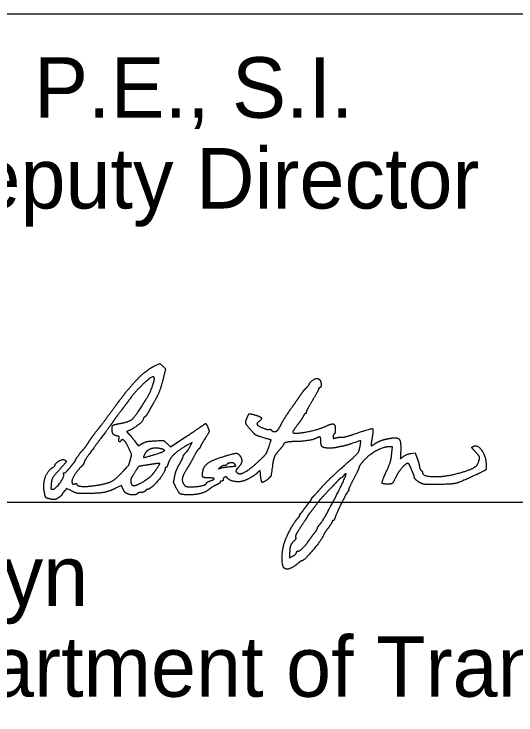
# Model space of a CAD drawing. Extents: x -6.2 to 37.4, y 0.2 to 22.2.
# Drawn here: x 25.269 to 26.43, y 7.512 to 9.134 of the extents above; entities that cross this region are included whole.
import ezdxf

# ---------------------------------------------------------------- set-up
doc = ezdxf.new("R2010")
doc.units = 0
doc.layers.add('SH_Data', color=7, linetype='Continuous')
doc.layers.add('SH_Text', color=7, linetype='Continuous')

msp = doc.modelspace()

# ---------------------------------------------------------------- linework, layer by layer
at = {"layer": 'SH_Data'}
for p, q in [((24.1087, 9.1337), (27.6087, 9.1337)), ((24.1087, 8.0042), (27.6087, 8.0042))]:
    msp.add_line(p, q, dxfattribs=at)
for points in [[(25.594, 8.3194), (25.6066, 8.3253), (25.613, 8.3189), (25.6194, 8.3126), (25.615, 8.2939)], [(25.5341, 8.1695), (25.5291, 8.1679), (25.5342, 8.1627)], [(25.5479, 8.1461), (25.5564, 8.1345), (25.5652, 8.1398)], [(25.623, 8.1398), (25.6312, 8.1321), (25.6674, 8.1563)], [(25.6769, 8.1345), (25.6814, 8.1424), (25.6759, 8.1395)], [(26.1428, 8.1186), (26.1443, 8.1324), (26.1365, 8.1324)], [(26.1866, 8.117), (26.1963, 8.1185), (26.2014, 8.105)], [(25.8387, 8.0708), (25.838, 8.0776), (25.8322, 8.0725)], [(25.4024, 8.0302), (25.3909, 8.0359), (25.3859, 8.0301)], [(25.5211, 8.0352), (25.5177, 8.0432), (25.5039, 8.0364)], [(25.9064, 7.8847), (25.9064, 7.8753), (25.914, 7.8796)]]:
    msp.add_lwpolyline(points, dxfattribs=at)
for points in [[(25.5044, 8.2276), (25.5341, 8.2682), (25.5759, 8.311), (25.594, 8.3194)], [(25.5926, 8.2936), (25.5889, 8.2973), (25.5504, 8.2616), (25.535, 8.2403)], [(25.5743, 8.2416), (25.5837, 8.2565), (25.5957, 8.2905), (25.5926, 8.2936)], [(25.615, 8.2939), (25.61, 8.2727), (25.6008, 8.2491), (25.5914, 8.2332)], [(25.952, 8.2775), (25.952, 8.2803), (25.9652, 8.2906), (25.969, 8.2907)], [(25.969, 8.2907), (25.971, 8.2907), (25.974, 8.2895), (25.9756, 8.2879)], [(25.9756, 8.2879), (25.979, 8.2844), (25.9794, 8.2692), (25.976, 8.2692)], [(25.9454, 8.2694), (25.9491, 8.273), (25.952, 8.2767), (25.952, 8.2775)], [(25.9317, 8.2522), (25.9356, 8.258), (25.9418, 8.2658), (25.9454, 8.2694)], [(25.9736, 8.2667), (25.9736, 8.2653), (25.9672, 8.2532), (25.9592, 8.2398)], [(25.976, 8.2692), (25.9747, 8.2692), (25.9736, 8.268), (25.9736, 8.2667)], [(25.535, 8.2403), (25.5314, 8.2353), (25.522, 8.2226), (25.514, 8.2122)], [(25.5637, 8.2249), (25.567, 8.2301), (25.5717, 8.2376), (25.5743, 8.2416)], [(25.91, 8.2212), (25.918, 8.2324), (25.9277, 8.2464), (25.9317, 8.2522)], [(25.9592, 8.2398), (25.9513, 8.2264), (25.9448, 8.214), (25.9448, 8.2123)], [(25.4643, 8.1741), (25.4732, 8.1854), (25.4912, 8.2095), (25.5044, 8.2276)], [(25.5139, 8.1863), (25.5345, 8.19), (25.5486, 8.2009), (25.5637, 8.2249)], [(25.5914, 8.2332), (25.5878, 8.2272), (25.5826, 8.2181), (25.5798, 8.2128)], [(25.514, 8.2122), (25.5061, 8.2017), (25.498, 8.1907), (25.496, 8.1877)], [(25.5798, 8.2128), (25.5769, 8.2075), (25.5731, 8.2023), (25.5713, 8.2013)], [(25.808, 8.1995), (25.8117, 8.2085), (25.8149, 8.2095), (25.8276, 8.2057)], [(25.8276, 8.2057), (25.8396, 8.2022), (25.8424, 8.196), (25.8348, 8.1902)], [(25.8887, 8.1876), (25.8925, 8.1948), (25.9021, 8.21), (25.91, 8.2212)], [(25.9428, 8.2092), (25.9418, 8.2092), (25.9394, 8.2062), (25.9376, 8.2026)], [(25.9448, 8.2123), (25.9448, 8.2106), (25.9439, 8.2092), (25.9428, 8.2092)], [(25.568, 8.1959), (25.568, 8.1921), (25.5423, 8.1721), (25.5341, 8.1695)], [(25.5713, 8.2013), (25.5695, 8.2002), (25.568, 8.1978), (25.568, 8.1959)], [(25.8178, 8.17), (25.8063, 8.1831), (25.804, 8.1899), (25.808, 8.1995)], [(25.8348, 8.1902), (25.832, 8.1881), (25.8305, 8.1853), (25.8315, 8.1839)], [(25.9376, 8.2026), (25.9358, 8.1989), (25.9297, 8.1899), (25.924, 8.1824)], [(25.4427, 8.1447), (25.4457, 8.1495), (25.4554, 8.1628), (25.4643, 8.1741)], [(25.496, 8.1877), (25.4941, 8.1847), (25.4787, 8.1638), (25.4619, 8.1412)], [(25.496, 8.1741), (25.496, 8.181), (25.5002, 8.1838), (25.5139, 8.1863)], [(25.507, 8.1577), (25.4999, 8.1595), (25.496, 8.1652), (25.496, 8.1741)], [(25.6674, 8.1563), (25.6873, 8.1695), (25.7049, 8.1814), (25.7065, 8.1828)], [(25.7065, 8.1828), (25.7111, 8.1865), (25.7135, 8.1857), (25.7165, 8.1791)], [(25.7165, 8.1791), (25.7208, 8.1694), (25.7199, 8.1653), (25.7096, 8.1495)], [(25.8315, 8.1839), (25.8342, 8.1801), (25.8541, 8.1719), (25.8587, 8.1727)], [(25.8794, 8.1714), (25.8807, 8.173), (25.8848, 8.1803), (25.8887, 8.1876)], [(25.924, 8.1824), (25.9183, 8.1749), (25.9136, 8.1677), (25.9136, 8.1663)], [(25.9136, 8.1663), (25.9136, 8.161), (25.9733, 8.172), (25.9912, 8.1805)], [(25.9912, 8.1805), (26.0042, 8.1867), (26.012, 8.1836), (26.012, 8.1722)], [(26.0544, 8.1615), (26.0947, 8.1753), (26.1007, 8.1737), (26.0965, 8.1498)], [(25.5121, 8.1515), (25.513, 8.155), (25.5118, 8.1565), (25.507, 8.1577)], [(25.5342, 8.1627), (25.537, 8.1599), (25.5432, 8.1524), (25.5479, 8.1461)], [(25.8412, 8.1549), (25.8305, 8.158), (25.8256, 8.1612), (25.8178, 8.17)], [(25.8587, 8.1727), (25.861, 8.1731), (25.8635, 8.1723), (25.8644, 8.1709)], [(25.8644, 8.1709), (25.8665, 8.1674), (25.8766, 8.1677), (25.8794, 8.1714)], [(26.0096, 8.1624), (26.0083, 8.1616), (26.0072, 8.1587), (26.0072, 8.1561)], [(26.012, 8.1722), (26.012, 8.1676), (26.011, 8.1632), (26.0096, 8.1624)], [(26.0256, 8.1544), (26.0297, 8.1543), (26.0427, 8.1574), (26.0544, 8.1615)], [(25.4264, 8.1229), (25.433, 8.1302), (25.4373, 8.1359), (25.4427, 8.1447)], [(25.4619, 8.1412), (25.4451, 8.1185), (25.4313, 8.0984), (25.4312, 8.0964)], [(25.5164, 8.1467), (25.514, 8.1428), (25.5108, 8.1464), (25.5121, 8.1515)], [(25.5352, 8.1281), (25.5291, 8.1418), (25.5193, 8.1514), (25.5164, 8.1467)], [(25.5652, 8.1398), (25.5718, 8.1436), (25.5793, 8.1453), (25.5945, 8.1462)], [(25.5945, 8.1462), (25.6148, 8.1474), (25.6149, 8.1473), (25.623, 8.1398)], [(25.7096, 8.1495), (25.7044, 8.1413), (25.7, 8.1337), (25.7, 8.1326)], [(25.858, 8.1311), (25.8637, 8.148), (25.8633, 8.1485), (25.8412, 8.1549)], [(25.9163, 8.1444), (25.9048, 8.1444), (25.892, 8.1406), (25.892, 8.1372)], [(25.967, 8.1518), (25.9614, 8.1488), (25.9312, 8.1444), (25.9163, 8.1444)], [(25.9784, 8.147), (25.9784, 8.1544), (25.9748, 8.1559), (25.967, 8.1518)], [(25.9978, 8.1294), (25.9854, 8.1294), (25.9784, 8.1357), (25.9784, 8.147)], [(26.0072, 8.1561), (26.0072, 8.1522), (26.0083, 8.1516), (26.0126, 8.153)], [(26.0126, 8.153), (26.0156, 8.1539), (26.0214, 8.1546), (26.0256, 8.1544)], [(26.0697, 8.1348), (26.0718, 8.1463), (26.07, 8.1467), (26.049, 8.1395)], [(26.0965, 8.1498), (26.0952, 8.1422), (26.0945, 8.1356), (26.0949, 8.1351)], [(26.1025, 8.139), (26.1097, 8.144), (26.128, 8.1504), (26.1416, 8.1525)], [(26.1416, 8.1525), (26.1563, 8.1548), (26.1639, 8.1444), (26.1632, 8.1231)], [(25.5385, 8.1036), (25.5411, 8.1134), (25.5408, 8.1156), (25.5352, 8.1281)], [(25.6062, 8.1285), (25.5954, 8.1306), (25.578, 8.1256), (25.5737, 8.119)], [(25.5956, 8.1149), (25.6149, 8.1208), (25.6189, 8.1259), (25.6062, 8.1285)], [(25.6759, 8.1395), (25.6525, 8.127), (25.6297, 8.1063), (25.6256, 8.0938)], [(25.6641, 8.1164), (25.6696, 8.1224), (25.6721, 8.1259), (25.6769, 8.1345)], [(25.6965, 8.1276), (25.6945, 8.126), (25.6914, 8.1218), (25.6896, 8.1183)], [(25.7, 8.1326), (25.7, 8.1315), (25.6984, 8.1292), (25.6965, 8.1276)], [(25.8397, 8.1038), (25.8502, 8.1138), (25.8543, 8.12), (25.858, 8.1311)], [(25.8827, 8.1252), (25.8742, 8.1157), (25.8685, 8.1031), (25.8669, 8.0904)], [(25.892, 8.1372), (25.892, 8.1363), (25.8878, 8.1309), (25.8827, 8.1252)], [(26.0144, 8.1308), (26.0111, 8.13), (26.0036, 8.1294), (25.9978, 8.1294)], [(26.0276, 8.1334), (26.0237, 8.1328), (26.0177, 8.1316), (26.0144, 8.1308)], [(26.0248, 8.0819), (26.0603, 8.1134), (26.0672, 8.1216), (26.0697, 8.1348)], [(26.049, 8.1395), (26.0412, 8.1368), (26.0316, 8.1341), (26.0276, 8.1334)], [(26.1365, 8.1324), (26.1238, 8.1324), (26.09, 8.114), (26.0778, 8.1004)], [(26.0949, 8.1351), (26.0954, 8.1346), (26.0988, 8.1364), (26.1025, 8.139)], [(26.3332, 8.1238), (26.3279, 8.1295), (26.3277, 8.1321), (26.3323, 8.1339)], [(26.3323, 8.1339), (26.3409, 8.1372), (26.3594, 8.1122), (26.3604, 8.096)], [(25.412, 8.1024), (25.412, 8.104), (25.4212, 8.117), (25.4264, 8.1229)], [(25.5737, 8.119), (25.5667, 8.1082), (25.5712, 8.1074), (25.5956, 8.1149)], [(25.6517, 8.0923), (25.6561, 8.0999), (25.6599, 8.1076), (25.6602, 8.1093)], [(25.6602, 8.1093), (25.6604, 8.1111), (25.6622, 8.1142), (25.6641, 8.1164)], [(25.6896, 8.1183), (25.6815, 8.1029), (25.6737, 8.0892), (25.6676, 8.0794)], [(25.7434, 8.1066), (25.7753, 8.1172), (25.7887, 8.1176), (25.7937, 8.1082)], [(26.1281, 8.0707), (26.1372, 8.0906), (26.1412, 8.1038), (26.1428, 8.1186)], [(26.1632, 8.1231), (26.1625, 8.1048), (26.1623, 8.105), (26.1701, 8.1105)], [(26.1701, 8.1105), (26.1739, 8.1132), (26.1813, 8.1161), (26.1866, 8.117)], [(26.3424, 8.0947), (26.3463, 8.1065), (26.3448, 8.1114), (26.3332, 8.1238)], [(25.3641, 8.0904), (25.3641, 8.0941), (25.3809, 8.1041), (25.3847, 8.1026)], [(25.3847, 8.1026), (25.3906, 8.1003), (25.3884, 8.0955), (25.374, 8.0795)], [(25.3975, 8.0832), (25.4029, 8.0898), (25.4083, 8.0965), (25.4096, 8.0981)], [(25.4096, 8.0981), (25.411, 8.0997), (25.412, 8.1016), (25.412, 8.1024)], [(25.4312, 8.0964), (25.4312, 8.0944), (25.4278, 8.0896), (25.4239, 8.0857)], [(25.5188, 8.0731), (25.5349, 8.0907), (25.5352, 8.0912), (25.5385, 8.1036)], [(25.5938, 8.0928), (25.5882, 8.0919), (25.5804, 8.0907), (25.5764, 8.0901)], [(25.5988, 8.0811), (25.6067, 8.0925), (25.6057, 8.0947), (25.5938, 8.0928)], [(25.6256, 8.0938), (25.6239, 8.0886), (25.6216, 8.0844), (25.6205, 8.0844)], [(25.6408, 8.0644), (25.6424, 8.0721), (25.6473, 8.0846), (25.6517, 8.0923)], [(25.7058, 8.0756), (25.7079, 8.0868), (25.7241, 8.1002), (25.7434, 8.1066)], [(25.7796, 8.0924), (25.7768, 8.0958), (25.7633, 8.095), (25.7611, 8.0913)], [(25.7636, 8.086), (25.7804, 8.0876), (25.7828, 8.0885), (25.7796, 8.0924)], [(25.7827, 8.075), (25.7881, 8.0663), (25.8148, 8.0798), (25.8397, 8.1038)], [(25.7937, 8.1082), (25.797, 8.1021), (25.7936, 8.0908), (25.7861, 8.0829)], [(26.0778, 8.1004), (26.072, 8.0939), (26.0672, 8.0874), (26.0672, 8.0858)], [(26.1797, 8.094), (26.1753, 8.094), (26.1571, 8.0735), (26.1524, 8.0633)], [(26.1852, 8.0874), (26.1838, 8.091), (26.1812, 8.094), (26.1797, 8.094)], [(26.2014, 8.105), (26.2042, 8.0975), (26.2064, 8.0894), (26.2064, 8.0869)], [(26.2935, 8.0704), (26.3172, 8.0766), (26.3401, 8.088), (26.3424, 8.0947)], [(26.3604, 8.096), (26.3613, 8.0806), (26.3586, 8.0775), (26.3352, 8.0665)], [(25.3392, 8.0287), (25.3362, 8.0473), (25.347, 8.0773), (25.3594, 8.085)], [(25.374, 8.0795), (25.3604, 8.0644), (25.3554, 8.0542), (25.3548, 8.0404)], [(25.3594, 8.085), (25.3619, 8.0866), (25.3641, 8.089), (25.3641, 8.0904)], [(25.3852, 8.0719), (25.3866, 8.0715), (25.3922, 8.0766), (25.3975, 8.0832)], [(25.4239, 8.0857), (25.414, 8.076), (25.4016, 8.0539), (25.4034, 8.0492)], [(25.5764, 8.0901), (25.5587, 8.0876), (25.5566, 8.0864), (25.5494, 8.0752)], [(25.569, 8.0525), (25.5801, 8.0594), (25.5911, 8.07), (25.5988, 8.0811)], [(25.6184, 8.0814), (25.6183, 8.0728), (25.5852, 8.034), (25.578, 8.034)], [(25.6205, 8.0844), (25.6193, 8.0844), (25.6184, 8.083), (25.6184, 8.0814)], [(25.6676, 8.0794), (25.6596, 8.0668), (25.6573, 8.0516), (25.6624, 8.0448)], [(25.7467, 8.0854), (25.7421, 8.0816), (25.7421, 8.0816), (25.7468, 8.0833)], [(25.7556, 8.0892), (25.7532, 8.0892), (25.7493, 8.0875), (25.7467, 8.0854)], [(25.7468, 8.0833), (25.7495, 8.0842), (25.757, 8.0854), (25.7636, 8.086)], [(25.7611, 8.0913), (25.7603, 8.0901), (25.7579, 8.0892), (25.7556, 8.0892)], [(25.7861, 8.0829), (25.7834, 8.0799), (25.7819, 8.0764), (25.7827, 8.075)], [(25.8669, 8.0904), (25.864, 8.0679), (25.8623, 8.0624), (25.8566, 8.0579)], [(25.9808, 8.0391), (25.988, 8.0475), (26.0078, 8.0667), (26.0248, 8.0819)], [(26.0672, 8.0858), (26.0672, 8.0842), (26.0613, 8.0714), (26.054, 8.0573)], [(26.1912, 8.0732), (26.1894, 8.0774), (26.1867, 8.0837), (26.1852, 8.0874)], [(26.2064, 8.0869), (26.2064, 8.0844), (26.2081, 8.0807), (26.21, 8.0787)], [(26.21, 8.0787), (26.212, 8.0767), (26.2136, 8.074), (26.2136, 8.0727)], [(25.3596, 8.0344), (25.3659, 8.0354), (25.386, 8.0638), (25.384, 8.069)], [(25.384, 8.069), (25.3833, 8.071), (25.3838, 8.0723), (25.3852, 8.0719)], [(25.4623, 8.0437), (25.4851, 8.0474), (25.5047, 8.0576), (25.5188, 8.0731)], [(25.5494, 8.0752), (25.5412, 8.0626), (25.538, 8.0527), (25.5402, 8.0469)], [(25.6428, 8.0404), (25.6383, 8.0495), (25.6381, 8.0517), (25.6408, 8.0644)], [(25.7194, 8.0604), (25.7079, 8.0604), (25.7038, 8.0649), (25.7058, 8.0756)], [(25.7227, 8.0535), (25.733, 8.0572), (25.7315, 8.0604), (25.7194, 8.0604)], [(25.7623, 8.0605), (25.7603, 8.0638), (25.7528, 8.0607), (25.7528, 8.0565)], [(25.7936, 8.052), (25.785, 8.0505), (25.7652, 8.0558), (25.7623, 8.0605)], [(25.8322, 8.0725), (25.8228, 8.0643), (25.8028, 8.0537), (25.7936, 8.052)], [(25.8566, 8.0579), (25.8449, 8.0487), (25.8405, 8.0519), (25.8387, 8.0708)], [(25.9782, 7.9553), (25.9858, 7.964), (26.039, 8.0678), (26.0369, 8.0699)], [(26.0255, 8.0604), (26.0247, 8.0604), (26.0207, 8.0569), (26.0167, 8.0526)], [(26.0313, 8.0658), (26.0288, 8.0628), (26.0262, 8.0604), (26.0255, 8.0604)], [(26.0369, 8.0699), (26.0362, 8.0706), (26.0337, 8.0687), (26.0313, 8.0658)], [(26.1355, 8.046), (26.1209, 8.046), (26.1193, 8.0514), (26.1281, 8.0707)], [(26.1524, 8.0633), (26.1466, 8.0509), (26.1418, 8.046), (26.1355, 8.046)], [(26.1945, 8.0636), (26.1945, 8.0647), (26.193, 8.0691), (26.1912, 8.0732)], [(26.2102, 8.048), (26.2031, 8.0514), (26.1947, 8.0598), (26.1945, 8.0636)], [(26.2136, 8.0727), (26.2136, 8.0642), (26.2642, 8.0627), (26.2935, 8.0704)], [(26.3352, 8.0665), (26.3004, 8.0502), (26.2794, 8.0454), (26.24, 8.045)], [(25.4034, 8.0492), (25.4044, 8.0468), (25.4067, 8.0459), (25.4097, 8.0467)], [(25.4097, 8.0467), (25.4123, 8.0474), (25.4144, 8.047), (25.4144, 8.0459)], [(25.4144, 8.0459), (25.4144, 8.0413), (25.4401, 8.0401), (25.4623, 8.0437)], [(25.5402, 8.0469), (25.5422, 8.0417), (25.5558, 8.0443), (25.569, 8.0525)], [(25.6624, 8.0448), (25.6653, 8.041), (25.6689, 8.04), (25.68, 8.04)], [(25.68, 8.04), (25.694, 8.04), (25.7144, 8.0451), (25.7144, 8.0486)], [(25.7144, 8.0486), (25.7144, 8.0496), (25.7182, 8.0518), (25.7227, 8.0535)], [(25.7402, 8.0458), (25.7329, 8.0425), (25.7253, 8.038), (25.721, 8.0345)], [(25.7456, 8.0507), (25.7456, 8.0494), (25.7432, 8.0472), (25.7402, 8.0458)], [(25.7492, 8.0532), (25.7473, 8.0532), (25.7456, 8.0521), (25.7456, 8.0507)], [(25.7528, 8.0565), (25.7528, 8.0547), (25.7512, 8.0532), (25.7492, 8.0532)], [(26.0167, 8.0526), (26.0126, 8.0483), (26.0021, 8.0372), (25.9933, 8.0279)], [(26.054, 8.0573), (26.0467, 8.0431), (26.0416, 8.0316), (26.0426, 8.0315)], [(26.24, 8.045), (26.2251, 8.0448), (26.2148, 8.0459), (26.2102, 8.048)], [(25.3558, 8.011), (25.3449, 8.013), (25.341, 8.0171), (25.3392, 8.0287)], [(25.3548, 8.0404), (25.3545, 8.0348), (25.3553, 8.0338), (25.3596, 8.0344)], [(25.3859, 8.0301), (25.3831, 8.027), (25.3808, 8.0235), (25.3808, 8.0226)], [(25.4332, 8.0244), (25.4176, 8.0244), (25.4117, 8.0255), (25.4024, 8.0302)], [(25.5039, 8.0364), (25.4883, 8.0287), (25.4631, 8.0244), (25.4332, 8.0244)], [(25.5293, 8.0246), (25.5266, 8.026), (25.5229, 8.0308), (25.5211, 8.0352)], [(25.5728, 8.0304), (25.5712, 8.0284), (25.5668, 8.0268), (25.5631, 8.0268)], [(25.578, 8.034), (25.5768, 8.034), (25.5745, 8.0324), (25.5728, 8.0304)], [(25.6745, 8.0213), (25.657, 8.0214), (25.65, 8.0256), (25.6428, 8.0404)], [(25.721, 8.0345), (25.7134, 8.0281), (25.689, 8.0212), (25.6745, 8.0213)], [(25.9623, 8.0187), (25.9652, 8.0215), (25.9735, 8.0307), (25.9808, 8.0391)], [(25.9933, 8.0279), (25.9844, 8.0187), (25.9745, 8.0074), (25.9712, 8.003)], [(26.0419, 8.0297), (26.0392, 8.0279), (26.0139, 7.9769), (26.011, 7.9674)], [(26.0426, 8.0315), (26.0436, 8.0315), (26.0433, 8.0307), (26.0419, 8.0297)], [(25.3725, 8.0151), (25.3659, 8.0107), (25.3623, 8.0098), (25.3558, 8.011)], [(25.3808, 8.0226), (25.3808, 8.0216), (25.3771, 8.0182), (25.3725, 8.0151)], [(25.5548, 8.0244), (25.5529, 8.0212), (25.5354, 8.0213), (25.5293, 8.0246)], [(25.5631, 8.0268), (25.5594, 8.0268), (25.5557, 8.0257), (25.5548, 8.0244)], [(25.9502, 8.0017), (25.9539, 8.0059), (25.9569, 8.0103), (25.9569, 8.0115)], [(25.9569, 8.0115), (25.9569, 8.0126), (25.9593, 8.0159), (25.9623, 8.0187)], [(25.94, 7.9884), (25.942, 7.9914), (25.9466, 7.9974), (25.9502, 8.0017)], [(25.9712, 8.003), (25.9632, 7.992), (25.9526, 7.9782), (25.9497, 7.9747)], [(25.9322, 7.9784), (25.9346, 7.9808), (25.9381, 7.9853), (25.94, 7.9884)], [(25.8963, 7.916), (25.9021, 7.9308), (25.9193, 7.9607), (25.9264, 7.9686)], [(25.9264, 7.9686), (25.9291, 7.9715), (25.9306, 7.974), (25.9297, 7.974)], [(25.9297, 7.974), (25.9288, 7.974), (25.9299, 7.976), (25.9322, 7.9784)], [(25.9472, 7.9708), (25.9472, 7.9702), (25.9409, 7.9603), (25.9332, 7.9487)], [(25.9497, 7.9747), (25.9483, 7.9731), (25.9472, 7.9713), (25.9472, 7.9708)], [(26.011, 7.9674), (26.0101, 7.9644), (26.0083, 7.962), (26.0071, 7.962)], [(25.9332, 7.9487), (25.9245, 7.9357), (25.9195, 7.9259), (25.9203, 7.9232)], [(25.9712, 7.945), (25.9712, 7.9463), (25.9744, 7.951), (25.9782, 7.9553)], [(26.0048, 7.9595), (26.0048, 7.9581), (26.0006, 7.9513), (25.9954, 7.9444)], [(26.0071, 7.962), (26.0058, 7.962), (26.0048, 7.9609), (26.0048, 7.9595)], [(25.961, 7.9292), (25.9667, 7.9365), (25.9712, 7.9437), (25.9712, 7.945)], [(25.9954, 7.9444), (25.9902, 7.9375), (25.985, 7.9295), (25.984, 7.9267)], [(25.8944, 7.8515), (25.8885, 7.8553), (25.8898, 7.8996), (25.8963, 7.916)], [(25.9166, 7.9146), (25.9106, 7.9094), (25.9064, 7.897), (25.9064, 7.8847)], [(25.9203, 7.9232), (25.9209, 7.9207), (25.9194, 7.917), (25.9166, 7.9146)], [(25.984, 7.9267), (25.9803, 7.9169), (25.9392, 7.8684), (25.9345, 7.8684)], [(25.9484, 7.9119), (25.9498, 7.914), (25.9554, 7.9218), (25.961, 7.9292)], [(25.9256, 7.8912), (25.9276, 7.89), (25.9442, 7.9051), (25.9484, 7.9119)], [(25.914, 7.8796), (25.9181, 7.882), (25.922, 7.8859), (25.9226, 7.8882)], [(25.9226, 7.8882), (25.9233, 7.8904), (25.9246, 7.8918), (25.9256, 7.8912)], [(25.9345, 7.8684), (25.9331, 7.8684), (25.9297, 7.8663), (25.927, 7.8638)], [(25.901, 7.8492), (25.8994, 7.8492), (25.8964, 7.8503), (25.8944, 7.8515)], [(25.927, 7.8638), (25.9208, 7.8581), (25.9049, 7.8492), (25.901, 7.8492)]]:
    msp.add_open_spline(points, degree=2, dxfattribs=at)

# ---------------------------------------------------------------- texts
at = {"layer": 'SH_Text'}
for s, p in [('Pat McColley, P.E., S.I.', (24.1087, 8.8937)), ('District       Deputy Director', (24.1087, 8.6837)), ('Pamela Boratyn', (24.1087, 7.7642)), ('Director, Department of Transportation', (24.1087, 7.5542))]:
    msp.add_text(s, height=0.14, dxfattribs=at).set_placement(p)

doc.saveas('drawing.dxf')
